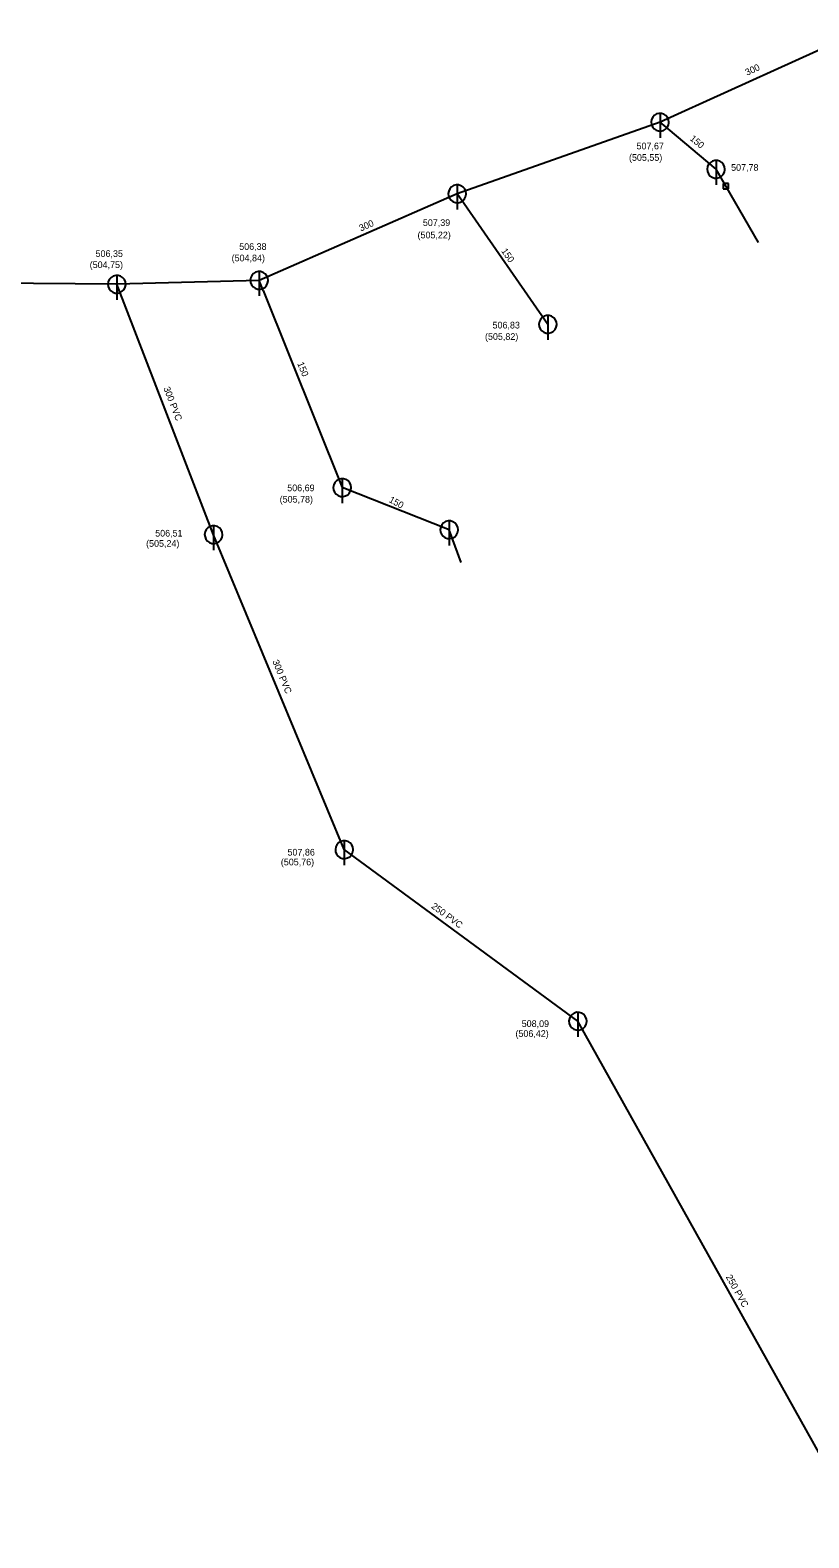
# Model space of a CAD drawing. Extents: x -476058 to -471893, y -1155786 to -1152000.
# Drawn here: x -475293.5 to -475206.1, y -1154419.8 to -1154250.5 of the extents above; entities that cross this region are included whole.
import ezdxf

# ---------------------------------------------------------------- set-up
doc = ezdxf.new("R2010")
doc.units = 0
for name, color, linetype in [('Vrstva 10', 7, 'Continuous'), ('Vrstva 13', 7, 'Continuous'), ('Vrstva 18', 7, 'Continuous'), ('Vrstva 19', 7, 'Continuous'), ('Vrstva 3', 7, 'Continuous'), ('Vrstva 4', 7, 'Continuous'), ('Vrstva 45', 7, 'Continuous'), ('Vrstva 50', 7, 'Continuous')]:
    doc.layers.add(name, color=color, linetype=linetype)

msp = doc.modelspace()

# ---------------------------------------------------------------- linework, layer by layer
at = {"layer": 'Vrstva 10'}
for p, q in [((-475222.79, -1154259.83), (-475222.79, -1154262.58)), ((-475216.51, -1154265.12), (-475216.51, -1154267.87)), ((-475245.56, -1154267.87), (-475245.56, -1154270.62)), ((-475283.76, -1154278.02), (-475283.76, -1154280.77)), ((-475267.78, -1154277.59), (-475267.78, -1154280.34)), ((-475235.39, -1154282.53), (-475235.39, -1154285.28)), ((-475258.46, -1154300.86), (-475258.46, -1154303.61)), ((-475246.46, -1154305.59), (-475246.46, -1154308.34)), ((-475272.9, -1154306.14), (-475272.9, -1154308.88)), ((-475258.23, -1154341.5), (-475258.23, -1154344.25)), ((-475232.02, -1154360.76), (-475232.02, -1154363.5))]:
    msp.add_line(p, q, dxfattribs=at)
for points in [[(-475221.79, -1154260.83), (-475221.83, -1154260.55), (-475221.95, -1154260.29), (-475222.13, -1154260.08), (-475222.36, -1154259.93), (-475222.64, -1154259.84), (-475222.92, -1154259.84), (-475223.19, -1154259.91), (-475223.43, -1154260.06), (-475223.62, -1154260.27), (-475223.74, -1154260.52), (-475223.79, -1154260.8), (-475223.76, -1154261.08), (-475223.65, -1154261.34), (-475223.47, -1154261.56), (-475223.24, -1154261.72), (-475222.97, -1154261.81), (-475222.69, -1154261.83), (-475222.42, -1154261.76), (-475222.17, -1154261.62), (-475221.98, -1154261.41), (-475221.85, -1154261.16), (-475221.79, -1154260.89), (-475221.79, -1154260.83)], [(-475215.51, -1154266.12), (-475215.55, -1154265.84), (-475215.67, -1154265.58), (-475215.85, -1154265.37), (-475216.09, -1154265.21), (-475216.36, -1154265.13), (-475216.64, -1154265.13), (-475216.91, -1154265.2), (-475217.15, -1154265.35), (-475217.34, -1154265.56), (-475217.46, -1154265.81), (-475217.51, -1154266.09), (-475217.48, -1154266.37), (-475217.37, -1154266.63), (-475217.19, -1154266.85), (-475216.96, -1154267.01), (-475216.69, -1154267.1), (-475216.41, -1154267.11), (-475216.14, -1154267.05), (-475215.89, -1154266.91), (-475215.7, -1154266.7), (-475215.57, -1154266.45), (-475215.51, -1154266.17), (-475215.51, -1154266.12)], [(-475244.56, -1154268.87), (-475244.6, -1154268.59), (-475244.72, -1154268.33), (-475244.9, -1154268.12), (-475245.14, -1154267.97), (-475245.41, -1154267.88), (-475245.69, -1154267.88), (-475245.96, -1154267.95), (-475246.2, -1154268.1), (-475246.39, -1154268.31), (-475246.51, -1154268.56), (-475246.56, -1154268.84), (-475246.53, -1154269.12), (-475246.42, -1154269.38), (-475246.24, -1154269.6), (-475246.01, -1154269.76), (-475245.74, -1154269.85), (-475245.46, -1154269.87), (-475245.19, -1154269.8), (-475244.94, -1154269.66), (-475244.75, -1154269.45), (-475244.62, -1154269.2), (-475244.56, -1154268.93), (-475244.56, -1154268.87)], [(-475282.76, -1154279.02), (-475282.8, -1154278.74), (-475282.91, -1154278.49), (-475283.1, -1154278.27), (-475283.33, -1154278.12), (-475283.6, -1154278.03), (-475283.88, -1154278.03), (-475284.16, -1154278.11), (-475284.4, -1154278.25), (-475284.59, -1154278.46), (-475284.71, -1154278.72), (-475284.76, -1154279), (-475284.73, -1154279.28), (-475284.62, -1154279.54), (-475284.44, -1154279.76), (-475284.21, -1154279.92), (-475283.94, -1154280.01), (-475283.66, -1154280.02), (-475283.38, -1154279.95), (-475283.14, -1154279.81), (-475282.94, -1154279.61), (-475282.81, -1154279.36), (-475282.76, -1154279.08), (-475282.76, -1154279.02)], [(-475266.78, -1154278.59), (-475266.82, -1154278.31), (-475266.94, -1154278.05), (-475267.12, -1154277.84), (-475267.35, -1154277.69), (-475267.62, -1154277.6), (-475267.91, -1154277.6), (-475268.18, -1154277.67), (-475268.42, -1154277.82), (-475268.61, -1154278.03), (-475268.73, -1154278.28), (-475268.78, -1154278.56), (-475268.75, -1154278.84), (-475268.64, -1154279.1), (-475268.46, -1154279.32), (-475268.23, -1154279.48), (-475267.96, -1154279.57), (-475267.68, -1154279.59), (-475267.41, -1154279.52), (-475267.16, -1154279.38), (-475266.97, -1154279.17), (-475266.84, -1154278.92), (-475266.78, -1154278.65), (-475266.78, -1154278.59)], [(-475234.39, -1154283.53), (-475234.43, -1154283.25), (-475234.55, -1154282.99), (-475234.73, -1154282.78), (-475234.97, -1154282.62), (-475235.23, -1154282.54), (-475235.52, -1154282.54), (-475235.79, -1154282.61), (-475236.03, -1154282.76), (-475236.22, -1154282.97), (-475236.34, -1154283.22), (-475236.39, -1154283.5), (-475236.36, -1154283.78), (-475236.25, -1154284.04), (-475236.07, -1154284.26), (-475235.84, -1154284.42), (-475235.57, -1154284.51), (-475235.29, -1154284.53), (-475235.02, -1154284.46), (-475234.77, -1154284.32), (-475234.58, -1154284.11), (-475234.45, -1154283.86), (-475234.39, -1154283.59), (-475234.39, -1154283.53)], [(-475257.46, -1154301.86), (-475257.5, -1154301.58), (-475257.62, -1154301.32), (-475257.8, -1154301.11), (-475258.04, -1154300.95), (-475258.31, -1154300.87), (-475258.59, -1154300.87), (-475258.86, -1154300.94), (-475259.1, -1154301.09), (-475259.29, -1154301.3), (-475259.42, -1154301.55), (-475259.46, -1154301.83), (-475259.43, -1154302.11), (-475259.32, -1154302.37), (-475259.14, -1154302.59), (-475258.91, -1154302.75), (-475258.65, -1154302.84), (-475258.36, -1154302.85), (-475258.09, -1154302.79), (-475257.85, -1154302.65), (-475257.65, -1154302.44), (-475257.52, -1154302.19), (-475257.46, -1154301.91), (-475257.46, -1154301.86)], [(-475245.46, -1154306.59), (-475245.5, -1154306.31), (-475245.62, -1154306.05), (-475245.8, -1154305.84), (-475246.04, -1154305.68), (-475246.31, -1154305.6), (-475246.59, -1154305.6), (-475246.86, -1154305.67), (-475247.1, -1154305.82), (-475247.29, -1154306.03), (-475247.41, -1154306.28), (-475247.46, -1154306.56), (-475247.43, -1154306.84), (-475247.32, -1154307.1), (-475247.14, -1154307.32), (-475246.91, -1154307.48), (-475246.64, -1154307.57), (-475246.36, -1154307.58), (-475246.09, -1154307.52), (-475245.84, -1154307.38), (-475245.65, -1154307.17), (-475245.52, -1154306.92), (-475245.46, -1154306.64), (-475245.46, -1154306.59)], [(-475271.9, -1154307.14), (-475271.93, -1154306.86), (-475272.05, -1154306.6), (-475272.23, -1154306.38), (-475272.47, -1154306.23), (-475272.74, -1154306.15), (-475273.02, -1154306.14), (-475273.29, -1154306.22), (-475273.53, -1154306.37), (-475273.72, -1154306.57), (-475273.85, -1154306.83), (-475273.9, -1154307.11), (-475273.86, -1154307.39), (-475273.75, -1154307.65), (-475273.58, -1154307.87), (-475273.35, -1154308.03), (-475273.08, -1154308.12), (-475272.79, -1154308.13), (-475272.52, -1154308.06), (-475272.28, -1154307.92), (-475272.08, -1154307.72), (-475271.95, -1154307.47), (-475271.9, -1154307.19), (-475271.9, -1154307.14)], [(-475257.23, -1154342.5), (-475257.27, -1154342.22), (-475257.39, -1154341.97), (-475257.57, -1154341.75), (-475257.81, -1154341.6), (-475258.08, -1154341.52), (-475258.36, -1154341.51), (-475258.63, -1154341.59), (-475258.87, -1154341.73), (-475259.06, -1154341.94), (-475259.19, -1154342.2), (-475259.23, -1154342.48), (-475259.2, -1154342.76), (-475259.09, -1154343.02), (-475258.92, -1154343.24), (-475258.68, -1154343.4), (-475258.42, -1154343.49), (-475258.13, -1154343.5), (-475257.86, -1154343.43), (-475257.62, -1154343.29), (-475257.42, -1154343.09), (-475257.29, -1154342.84), (-475257.23, -1154342.56), (-475257.23, -1154342.5)], [(-475231.02, -1154361.76), (-475231.06, -1154361.48), (-475231.18, -1154361.22), (-475231.36, -1154361.01), (-475231.6, -1154360.85), (-475231.87, -1154360.77), (-475232.15, -1154360.76), (-475232.42, -1154360.84), (-475232.66, -1154360.99), (-475232.85, -1154361.2), (-475232.97, -1154361.45), (-475233.02, -1154361.73), (-475232.99, -1154362.01), (-475232.88, -1154362.27), (-475232.7, -1154362.49), (-475232.47, -1154362.65), (-475232.2, -1154362.74), (-475231.92, -1154362.75), (-475231.65, -1154362.68), (-475231.4, -1154362.54), (-475231.21, -1154362.34), (-475231.08, -1154362.09), (-475231.02, -1154361.81), (-475231.02, -1154361.76)]]:
    msp.add_lwpolyline(points, dxfattribs=at)
at = {"layer": 'Vrstva 13'}
for p, q in [((-475215.11, -1154267.7), (-475215.72, -1154267.7)), ((-475215.72, -1154267.7), (-475215.72, -1154268.3)), ((-475215.72, -1154268.3), (-475215.11, -1154268.3)), ((-475215.11, -1154268.3), (-475215.11, -1154267.7))]:
    msp.add_line(p, q, dxfattribs=at)
at = {"layer": 'Vrstva 45'}
for points in [[(-475200, -1154250.5), (-475222.79, -1154260.83)], [(-475222.79, -1154260.83), (-475245.56, -1154268.87)], [(-475245.56, -1154268.87), (-475267.78, -1154278.59)], [(-475267.78, -1154278.59), (-475283.76, -1154279.02)], [(-475283.76, -1154279.02), (-475325.84, -1154278.68)], [(-475272.9, -1154307.14), (-475283.76, -1154279.02)], [(-475258.23, -1154342.5), (-475272.9, -1154307.14)], [(-475232.02, -1154361.76), (-475258.23, -1154342.5)], [(-475199.61, -1154419.76), (-475232.02, -1154361.76)]]:
    msp.add_lwpolyline(points, dxfattribs=at)
at = {"layer": 'Vrstva 50'}
for points in [[(-475211.74, -1154274.32), (-475216.51, -1154266.12), (-475221.87, -1154261.59), (-475222.79, -1154260.83)], [(-475235.39, -1154283.53), (-475244.79, -1154269.98), (-475245.56, -1154268.87)], [(-475267.33, -1154279.72), (-475267.78, -1154278.59)], [(-475267.33, -1154279.72), (-475258.46, -1154301.86)], [(-475245.11, -1154310.26), (-475246.46, -1154306.59), (-475258.46, -1154301.86)]]:
    msp.add_lwpolyline(points, dxfattribs=at)

# ---------------------------------------------------------------- texts
at = {"layer": 'Vrstva 18'}
for s, rotation, p in [('300 ', 24.3833, (-475213.04, -1154255.63)), ('300 ', 23.6267, (-475256.37, -1154273.11)), ('300 PVC', 291.1257, (-475278.54, -1154290.69)), ('300 PVC', 292.5153, (-475266.32, -1154321.36)), ('250 PVC', 323.7023, (-475248.53, -1154349)), ('250 PVC', 299.1983, (-475215.44, -1154390.46))]:
    msp.add_text(s, height=0.75, rotation=rotation, dxfattribs=at).set_placement(p)
at = {"layer": 'Vrstva 19'}
for rotation, p in [(320.4318, (-475219.51, -1154262.78)), (304.7483, (-475240.65, -1154275.3)), (291.9165, (-475263.52, -1154287.92)), (331.3155, (-475253.29, -1154303.44))]:
    msp.add_text('150 ', height=0.75, rotation=rotation, dxfattribs=at).set_placement(p)
at = {"layer": 'Vrstva 3'}
for s, p in [('507,67', (-475225.43, -1154263.88)), ('507,78', (-475214.82, -1154266.29)), ('507,39', (-475249.41, -1154272.48)), ('506,35', (-475286.14, -1154275.96)), ('506,38', (-475270.02, -1154275.17)), ('506,83', (-475241.59, -1154283.99)), ('506,69', (-475264.63, -1154302.26)), ('506,51', (-475279.45, -1154307.35)), ('507,86', (-475264.6, -1154343.16)), ('508,09', (-475238.32, -1154362.41))]:
    msp.add_text(s, height=0.75, dxfattribs=at).set_placement(p)
at = {"layer": 'Vrstva 4'}
for s, p in [('(505,55)', (-475226.28, -1154265.17)), ('(505,22)', (-475250.01, -1154273.87)), ('(504,75)', (-475286.8, -1154277.21)), ('(504,84)', (-475270.87, -1154276.45)), ('(505,82)', (-475242.44, -1154285.27)), ('(505,78)', (-475265.48, -1154303.54)), ('(505,24)', (-475280.47, -1154308.5)), ('(505,76)', (-475265.35, -1154344.26)), ('(506,42)', (-475239.02, -1154363.52))]:
    msp.add_text(s, height=0.75, dxfattribs=at).set_placement(p)

doc.saveas('drawing.dxf')
